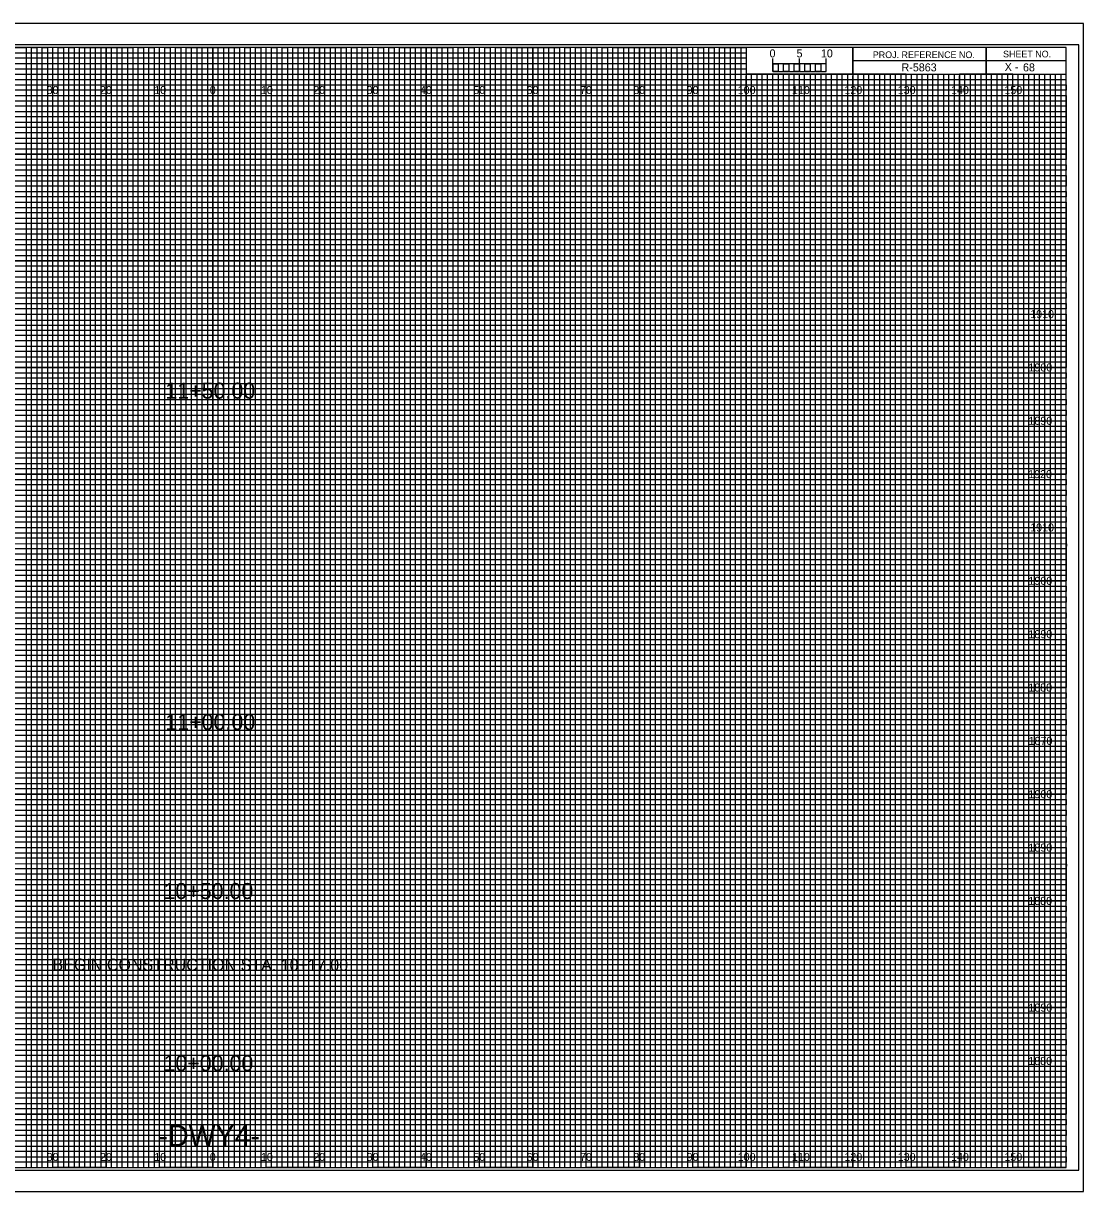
# Model space of a CAD drawing. Extents: x -13 to 323, y -4 to 214.
# Drawn here: x 124.5 to 323.3, y -4.5 to 214.5 of the extents above; entities that cross this region are included whole.
import ezdxf

# ---------------------------------------------------------------- set-up
doc = ezdxf.new("R2010")
doc.units = 0
for name, color, linetype in [('Prop XS Alignment Label', 7, 'Continuous'), ('Prop XS Bar Scale Labels', 7, 'Continuous'), ('Prop XS Elevation Labels', 7, 'Continuous'), ('Prop XS Offset Labels', 7, 'Continuous'), ('Prop XS Project Number', 7, 'Continuous'), ('Prop XS SE Text', 7, 'Continuous'), ('Prop XS Sheet Number', 7, 'Continuous'), ('Prop XS Station Labels', 7, 'Continuous'), ('Sheet Cross Section CELL', 7, 'Continuous'), ('Sheet Cross Section Grid Major CELL', 7, 'Continuous'), ('Sheet Cross Section Grid Middle CELL', 7, 'Continuous'), ('Sheet Cross Section Grid Minor 1 CELL', 7, 'Continuous'), ('Sheet Cross Section Grid Minor 2 CELL', 7, 'Continuous'), ('Sheet Cross Section Scale CELL', 7, 'Continuous'), ('Sheet Cutting Line CELL', 7, 'Continuous'), ('Sheet DOT Grid CELL', 7, 'Continuous'), ('Sheet Plot Border Inside CELL', 7, 'Continuous'), ('Sheet Plot Border Outside CELL', 7, 'Continuous')]:
    doc.layers.add(name, color=color, linetype=linetype)

msp = doc.modelspace()

# ---------------------------------------------------------------- linework, layer by layer
at = {"layer": 'Sheet Cross Section CELL'}
for p, q in [((305, 210), (305, 205)), ((305, 205), (305, 210)), ((280, 207.5), (280, 205)), ((320, 207.49), (280, 207.49)), ((280, 205), (320, 205))]:
    msp.add_line(p, q, dxfattribs=at)
for points in [[(320, 210), (0, 210), (0, 0), (320, 0)], [(280, 210), (260, 210), (260, 205.03), (280, 205.03)], [(320, 210), (280, 210), (280, 205), (320, 205)]]:
    msp.add_lwpolyline(points, close=True, dxfattribs=at)
at = {"layer": 'Sheet Cross Section Grid Major CELL'}
for p, q in [((130, 210), (120, 210)), ((130, 0), (130, 210)), ((150, 210), (140, 210)), ((140, 210), (140, 0)), ((150, 0), (150, 210)), ((170, 210), (160, 210)), ((160, 210), (160, 0)), ((170, 0), (170, 210)), ((190, 210), (180, 210)), ((180, 210), (180, 0)), ((190, 0), (190, 210)), ((210, 210), (200, 210)), ((200, 210), (200, 0)), ((210, 0), (210, 210)), ((230, 210), (220, 210)), ((220, 210), (220, 0)), ((230, 0), (230, 210)), ((250, 210), (240, 210)), ((240, 210), (240, 0)), ((250, 0), (250, 210)), ((260, 210), (260, 0)), ((270, 0), (270, 205)), ((290, 205), (280, 205)), ((280, 205), (280, 0)), ((290, 0), (290, 205)), ((310, 205), (300, 205)), ((300, 205), (300, 0)), ((310, 0), (310, 205)), ((140, 0), (130, 0)), ((160, 0), (150, 0)), ((180, 0), (170, 0)), ((200, 0), (190, 0)), ((220, 0), (210, 0)), ((240, 0), (230, 0)), ((260, 0), (250, 0)), ((280, 0), (270, 0)), ((300, 0), (290, 0)), ((320, 0), (310, 0)), ((320, 0), (320, 0))]:
    msp.add_line(p, q, dxfattribs=at)
for points in [[(0, 200), (320, 200), (320, 190), (0, 190)], [(0, 180), (320, 180), (320, 170), (0, 170)], [(0, 160), (320, 160), (320, 150), (0, 150)], [(0, 140), (320, 140), (320, 130), (0, 130)], [(0, 120), (320, 120), (320, 110), (0, 110)], [(0, 100), (320, 100), (320, 90), (0, 90)], [(0, 80), (320, 80), (320, 70), (0, 70)], [(0, 60), (320, 60), (320, 50), (0, 50)], [(0, 40), (320, 40), (320, 30), (0, 30)], [(0, 20), (320, 20), (320, 10), (0, 10)]]:
    msp.add_lwpolyline(points, dxfattribs=at)
at = {"layer": 'Sheet Cross Section Grid Middle CELL'}
for points in [[(115, 210), (125, 210), (125, 0), (135, 0), (135, 210), (145, 210), (145, 0), (155, 0), (155, 210), (165, 210), (165, 0), (175, 0), (175, 210), (185, 210), (185, 0), (195, 0), (195, 210), (205, 210), (205, 0), (215, 0), (215, 210), (225, 210), (225, 0), (235, 0), (235, 210), (245, 210), (245, 0), (255, 0), (255, 210), (259.93, 210), (260, 210), (260, 205), (264.99, 205), (264.99, 0), (275, 0), (275, 205), (285, 205), (285, 0), (295, 0), (295, 205), (305, 205), (305, 0), (315, 0), (315, 205)], [(0, 205), (275, 205)], [(0, 185), (320, 185), (320, 195), (0, 195)], [(0, 165), (320, 165), (320, 175), (0, 175)], [(0, 145), (320, 145), (320, 155), (0, 155)], [(0, 125), (320, 125), (320, 135), (0, 135)], [(0, 105), (320, 105), (320, 115), (0, 115)], [(0, 85), (320, 85), (320, 95), (0, 95)], [(0, 65), (320, 65), (320, 75), (0, 75)], [(0, 45), (320, 45), (320, 55), (0, 55)], [(0, 25), (320, 25), (320, 35), (0, 35)], [(0, 5), (320, 5), (320, 15), (0, 15)]]:
    msp.add_lwpolyline(points, dxfattribs=at)
at = {"layer": 'Sheet Cross Section Grid Minor 1 CELL'}
for p, q in [((0, 209), (260, 209)), ((260, 209), (260, 207.98)), ((260, 207.98), (0, 207.98)), ((0, 207), (260, 207)), ((260, 205.89), (0, 205.89)), ((260, 207), (260, 205.89)), ((0, 204), (320, 204))]:
    msp.add_line(p, q, dxfattribs=at)
for points in [[(0, 203), (270, 203), (320, 203), (320, 202), (0, 202)], [(0, 201), (320, 201), (320, 199), (0, 199)], [(0, 198), (320, 198), (320, 197), (0, 196.98)], [(0, 196), (320, 196), (320, 194), (0, 194)], [(0, 193), (320, 193), (320, 192), (0, 192)], [(0, 191), (320, 191), (320, 189), (0, 189)], [(0, 188), (320, 188), (320, 187), (0, 187)], [(0, 186), (320, 186), (320, 184), (0, 184)], [(0, 183), (320, 183), (320, 182), (0, 182)], [(0, 181), (320, 181), (320, 179), (0, 179)], [(0, 178), (320, 178), (320, 177), (0, 177)], [(0, 176), (320, 176), (320, 173.95), (320, 173), (320, 172), (0, 172)], [(0, 174), (320, 174), (320, 173), (0, 173)], [(0, 171), (320, 171), (320, 169), (0, 169.03)], [(0, 169.03), (320, 169), (320, 168), (0, 168)], [(0, 167), (320, 167), (320, 166), (0, 166)], [(0, 164), (320, 164), (320, 163), (0, 163)], [(0, 162), (320, 162), (320, 161), (0, 161)], [(-0.07, 158.89), (320, 158.89), (320, 157.88), (-0.07, 157.88)], [(0, 157), (320, 157), (320, 156), (0, 156)], [(0, 154), (320, 154), (320, 153), (0, 153)], [(0, 152), (320, 152), (320, 151), (0, 151)], [(0, 149), (320, 149), (320, 148), (0, 148)], [(0, 147), (320, 147), (320, 146), (0, 146)], [(0, 144), (320, 144), (320, 143), (0, 143)], [(0, 142), (320, 142), (320, 141), (0, 141)], [(0, 139), (320, 139), (319.99, 137.98), (0, 138)], [(0, 137), (320, 137), (320, 136), (0, 136)], [(0, 134), (320, 134), (320, 133), (0, 133)], [(0, 132), (320, 132), (320, 131), (0, 131)], [(0, 129), (320, 129), (320, 128), (0, 128)], [(0, 127), (320, 127), (320, 126), (0, 126)], [(0, 124), (320, 124), (320, 123), (0, 123)], [(0, 122), (320, 122), (320, 121), (0, 121)], [(0, 119), (320, 119), (320, 118), (0, 118)], [(0, 116.99), (320.07, 116.91), (320, 116), (0, 116)], [(0, 114), (320, 114), (320, 113), (0, 113)], [(0, 112), (320, 112), (320, 111), (0, 111)], [(0, 109), (320, 109), (320, 108), (0, 108)], [(0, 107), (320, 107), (320, 106), (0, 106)], [(0, 104), (320, 104), (320, 103), (0, 103)], [(0, 102), (320, 102), (320, 101), (0, 101)], [(0, 99), (320, 99), (320, 98), (0, 98)], [(0, 97), (320, 97), (320, 96), (0, 96)], [(0, 94), (320, 94), (320, 93), (0, 93)], [(0, 92), (320, 92), (320, 91), (0, 91)], [(0, 89), (320, 89), (320, 88), (0, 88)], [(0, 87), (320, 87), (320, 86), (0, 86)], [(0, 84), (320, 84), (320, 83), (0, 83)], [(0, 82), (320, 82), (320, 81), (0, 81)], [(0, 79), (320, 79), (319.99, 77.98), (0, 78)], [(0, 77), (320, 77), (320, 76), (0, 76)], [(0, 74), (320, 74), (320, 73), (0, 73)], [(0, 72), (320, 72), (320, 71), (0, 71)], [(0, 69), (320, 69), (320, 68), (0, 68)], [(0, 67), (320, 67), (320, 66), (0, 66)], [(0, 64), (320, 64), (320, 63), (0, 63)], [(0, 62), (320, 62), (320, 61), (0, 61)], [(0, 59), (320, 59), (320, 58), (0, 58)], [(0, 56.99), (320.07, 56.91), (320, 56), (0, 56)], [(0, 54), (320, 54), (320, 53), (0, 53)], [(0, 52), (320, 52), (320, 51), (0, 51)], [(0, 49), (320, 49), (320, 48), (0, 48)], [(0, 47), (320, 47), (320, 46), (0, 46)], [(0, 44), (320, 44), (320, 43), (0, 43)], [(0, 42), (320, 42), (320, 41), (0, 41)], [(0, 39), (320, 39), (320, 38), (0, 38)], [(0, 37), (320, 37), (320, 36), (0, 36)], [(0, 34), (320, 34), (320, 33), (0, 33)], [(0, 32), (320, 32), (320, 31), (0, 31)], [(0, 29), (320, 29), (320, 28), (0, 28)], [(0, 27), (320, 27), (320, 26), (0, 26)], [(0, 24), (320, 24), (320, 23), (0, 23)], [(0, 22), (320, 22), (320, 21), (0, 21)], [(0, 19), (320, 19), (320, 18), (0, 18)], [(0, 17), (320, 17), (320, 16), (0, 16)], [(0, 14), (320, 14), (320, 13), (0, 13)], [(0, 12), (320, 12), (320, 11), (0, 11)], [(0, 9), (320, 9), (320, 8), (0, 8)], [(0, 7), (320, 7), (320, 6), (0, 6)], [(0, 4), (320, 4), (320, 3), (0, 3)], [(0, 2), (320, 2), (320, 1), (0, 1)]]:
    msp.add_lwpolyline(points, dxfattribs=at)
at = {"layer": 'Sheet Cross Section Grid Minor 2 CELL'}
for p, q in [((267, 205), (266.01, 205)), ((266.01, 205), (266.01, 0)), ((267, 0), (267, 205)), ((269, 205), (268, 205)), ((268, 205), (268, 0)), ((269, 0), (269, 205)), ((266.01, 0), (265, 0)), ((268, 0), (267, 0))]:
    msp.add_line(p, q, dxfattribs=at)
for points in [[(125, 0), (126, 0), (126, 210), (127, 210), (127, 0)], [(127, 0), (128, 0), (128, 210), (129, 210), (129, 0)], [(130, 0), (131, 0), (131, 210), (132, 210), (132, 0)], [(132, 0), (133, 0), (133, 210), (134, 210), (134, 0)], [(135, 0), (136, 0), (136, 210), (137, 210), (137, 0)], [(137, 0), (138, 0), (138, 210), (139, 210), (139, 0)], [(140, 0), (141, 0), (141, 210), (142, 210), (142, 0)], [(142, 0), (143, 0), (143, 210), (144, 210), (144, 0)], [(145, 0), (146, 0), (146, 210), (147, 210), (147, 0)], [(147, 0), (148, 0), (148, 210), (149, 210), (149, 0)], [(150, 0), (151, 0), (151, 210), (152, 210), (152, 0)], [(152, 0), (153, 0), (153, 210), (154, 210), (154, 0)], [(155, 0), (156, 0), (156, 210), (157, 210), (157, 0)], [(157, 0), (158, 0), (158, 210), (159, 210), (159, 0)], [(160, 0), (161, 0), (161, 210), (162, 210), (162, 0)], [(162, 0), (163, 0), (163, 210), (164, 210), (164, 0)], [(165, 0), (166, 0), (166, 210), (167, 210), (167, 0)], [(167, 0), (168, 0), (168, 210), (169, 210), (169, 0)], [(170, 0), (171, 0), (171, 210), (172, 210), (172, 0)], [(172, 0), (173, 0), (173, 210), (174, 210), (174, 0)], [(175, 0), (176, 0), (176, 210), (177, 210), (177, 0)], [(177, 0), (178, 0), (178, 210), (179, 210), (179, 0)], [(180, 0), (181, 0), (181, 210), (182, 210), (182, 0)], [(182, 0), (183, 0), (183, 210), (184, 210), (184, 0)], [(185, 0), (186, 0), (186, 210), (187, 210), (187, 0)], [(187, 0), (188, 0), (188, 210), (189, 210), (189, 0)], [(190, 0), (191, 0), (191, 210), (192, 210), (192, 0)], [(192, 0), (193, 0), (193, 210), (194, 210), (194, 0)], [(195, 0), (196, 0), (196, 210), (197, 210), (197, 0)], [(197, 0), (198, 0), (198, 210), (199, 210), (199, 0)], [(200, 0), (201, 0), (201, 210), (202, 210), (202, 0)], [(202, 0), (203, 0), (203, 210), (204, 210), (204, 0)], [(205, 0), (206, 0), (206, 210), (207, 210), (207, 0)], [(207, 0), (208, 0), (208, 210), (209, 210), (209, 0)], [(210, 0), (211, 0), (211, 210), (212, 210), (212, 0)], [(212, 0), (213, 0), (213, 210), (214, 210), (214, 0)], [(215, 0), (216, 0), (216, 210), (217, 210), (217, 0)], [(217, 0), (218, 0), (218, 210), (219, 210), (219, 0)], [(220, 0), (221, 0), (221, 210), (222, 210), (222, 0)], [(222, 0), (223, 0), (223, 210), (224, 210), (224, 0)], [(225, 0), (226, 0), (226, 210), (227, 210), (227, 0)], [(227, 0), (228, 0), (228, 210), (229, 210), (229, 0)], [(230, 0), (231, 0), (231, 210), (232, 210), (232, 0)], [(232, 0), (233, 0), (233, 210), (234, 210), (234, 0)], [(235, 0), (236, 0), (236, 210), (237, 210), (237, 0)], [(237, 0), (238, 0), (238, 210), (239, 210), (239, 0)], [(240, 0), (241, 0), (241, 210), (242, 210), (242, 0)], [(242, 0), (243, 0), (243, 210), (244, 210), (244, 0)], [(245, 0), (246, 0), (246, 210), (247, 210), (247, 0)], [(247, 0), (248, 0), (248, 210), (249, 210), (249, 0)], [(250, 0), (251, 0), (251, 210), (252, 210), (252, 0)], [(252, 0), (253, 0), (253, 210), (254, 210), (254, 0)], [(255, 0), (256, 0), (256, 210), (257, 210), (257, 0)], [(257, 0), (258, 0), (258, 210), (259, 210), (259, 0)], [(260, 0), (261, 0), (261, 205), (262.02, 205), (262.02, 0)], [(262, 0), (263, 0), (263, 205), (263.99, 205), (263.99, 0)], [(270, 0), (270.98, 0), (270.98, 205), (272, 205), (272, 0)], [(272, 0), (273, 0), (273, 205), (274.05, 205), (274.05, 0)], [(275, 0), (276, 0), (276, 205), (277, 205), (277, 0)], [(277, 0), (278, 0), (278, 205), (279, 205), (279, 0)], [(280, 0), (281, 0), (281, 205), (282, 205), (282, 0)], [(282, 0), (283, 0), (283, 205), (284, 205), (284, 0)], [(285, 0), (286, 0), (286, 205), (287, 205), (287, 0)], [(287, 0), (288, 0), (288, 205), (289, 205), (289, 0)], [(290, 0), (291, 0), (291, 205), (292, 205), (292, 0)], [(292, 0), (293, 0), (293, 205), (294, 205), (294, 0)], [(295, 0), (296, 0), (296, 205), (297, 205), (297, 0)], [(297, 0), (298, 0), (298, 205), (299, 205), (299, 0)], [(300, 0), (301, 0), (301, 205), (302, 205), (302, 0)], [(302, 0), (303, 0), (303, 205), (304, 205), (304, 0)], [(305, 0), (306, 0), (306, 205), (307, 205), (307, 0)], [(307, 0), (308, 0), (308, 205), (309, 205), (309, 0)], [(310, 0), (311, 0), (311, 205), (312, 205), (312, 0)], [(312, 0), (313, 0), (313, 205), (314, 205), (314, 0)], [(315, 0), (316, 0), (316, 205), (317, 205), (317, 0)], [(317, 0), (318, 0), (318, 205), (319, 205), (319, 0)]]:
    msp.add_lwpolyline(points, dxfattribs=at)
at = {"layer": 'Sheet Cross Section Scale CELL'}
for p, q in [((265, 205.49), (265, 207.9)), ((265, 206.9), (265, 207.9)), ((270, 205.49), (270, 207.9)), ((275, 205.49), (275, 207.9)), ((275, 206.9), (275, 207.9))]:
    msp.add_line(p, q, dxfattribs=at)
for points in [[(275, 206.9), (265, 206.9), (265, 205.49), (275, 205.49)], [(265, 206.9), (266, 206.9), (266, 205.49), (265, 205.49)], [(267, 206.9), (268, 206.9), (268, 205.49), (267, 205.49)], [(269, 206.9), (270, 206.9), (270, 205.49), (269, 205.49)], [(271, 206.9), (272, 206.9), (272, 205.49), (271, 205.49)], [(273, 206.9), (274, 206.9), (274, 205.49), (273, 205.49)]]:
    msp.add_lwpolyline(points, close=True, dxfattribs=at)
at = {"layer": 'Sheet Cutting Line CELL'}
for p, q in [((323.3, 214.5), (-13.4, 214.5)), ((-13.4, -4.5), (323.3, -4.5))]:
    msp.add_line(p, q, dxfattribs=at)
at = {"layer": 'Sheet DOT Grid CELL'}
for p, q in [((130, 0), (130, 210)), ((140, 0), (140, 210)), ((150, 0), (150, 210)), ((160, 0), (160, 210)), ((170, 0), (170, 210)), ((180, 0), (180, 210)), ((190, 0), (190, 210)), ((200, 0), (200, 210)), ((210, 0), (210, 210)), ((220, 0), (220, 210)), ((230, 0), (230, 210)), ((240, 0), (240, 210)), ((250, 0), (250, 210)), ((260, 0), (260, 204.69)), ((270, 0), (270, 204.69)), ((280, 0), (280, 204.69)), ((290, 0), (290, 204.69)), ((300, 0), (300, 204.69)), ((310, 0), (310, 204.69)), ((0, 200), (320, 200)), ((0, 190), (320, 190)), ((0, 180), (320, 180)), ((0, 170), (320, 170)), ((0, 160), (320, 160)), ((0, 150), (320, 150)), ((0, 140), (320, 140)), ((0, 130), (320, 130)), ((0, 120), (320, 120)), ((0, 110), (320, 110)), ((0, 100), (320, 100)), ((0, 90), (320, 90)), ((0, 80), (320, 80)), ((0, 70), (320, 70)), ((0, 60), (320, 60)), ((0, 50), (320, 50)), ((0, 40), (320, 40)), ((0, 30), (320, 30)), ((0, 20), (320, 20)), ((0, 10), (320, 10))]:
    msp.add_line(p, q, dxfattribs=at)
at = {"layer": 'Sheet Plot Border Inside CELL'}
msp.add_lwpolyline([(-10.8, -0.5), (322.4, -0.5), (322.4, 210.5), (-10.8, 210.5)], close=True, dxfattribs=at)
at = {"layer": 'Sheet Plot Border Outside CELL'}
msp.add_lwpolyline([(-13.4, -4.5), (323.3, -4.5), (323.3, 214.5), (-13.4, 214.5)], close=True, dxfattribs=at)

# ---------------------------------------------------------------- texts
at = {"layer": 'Prop XS Alignment Label'}
msp.add_text('-DWY4-', height=4, dxfattribs=at).set_placement((149.85, 4))
at = {"layer": 'Prop XS Bar Scale Labels'}
for s, p in [('5', (269.47, 208.12)), ('10', (274.04, 208.12))]:
    msp.add_text(s, height=1.5, dxfattribs=at).set_placement(p)
at = {"layer": 'Prop XS Elevation Labels'}
for s, p in [('1910', (313.28, 159.25)), ('1900', (312.95, 149.25)), ('1890', (312.95, 139.25)), ('1920', (312.9, 129.25)), ('1910', (313.28, 119.25)), ('1900', (312.95, 109.25)), ('1890', (312.95, 99.25)), ('1880', (312.92, 89.25)), ('1870', (312.98, 79.25)), ('1900', (312.95, 69.25)), ('1890', (312.95, 59.25)), ('1880', (312.92, 49.25)), ('1890', (312.95, 29.25)), ('1880', (312.92, 19.25))]:
    msp.add_text(s, height=1.5, dxfattribs=at).set_placement(p)
at = {"layer": 'Prop XS Offset Labels'}
for s, p in [('30', (128.86, 201.25)), ('20', (138.86, 201.25)), ('10', (149.04, 201.25)), ('0', (159.45, 201.25)), ('0', (159.45, 201.25)), ('10', (169.04, 201.25)), ('20', (178.86, 201.25)), ('30', (188.86, 201.25)), ('40', (198.86, 201.25)), ('50', (208.86, 201.25)), ('60', (218.86, 201.25)), ('70', (228.86, 201.25)), ('80', (238.86, 201.25)), ('90', (248.86, 201.25)), ('100', (258.44, 201.25)), ('110', (268.62, 201.25)), ('120', (278.44, 201.25)), ('130', (288.44, 201.25)), ('140', (298.44, 201.25)), ('150', (308.44, 201.25)), ('30', (128.86, 1.25)), ('20', (138.86, 1.25)), ('10', (149.04, 1.25)), ('0', (159.45, 1.25)), ('0', (159.45, 1.25)), ('10', (169.04, 1.25)), ('20', (178.86, 1.25)), ('30', (188.86, 1.25)), ('40', (198.86, 1.25)), ('50', (208.86, 1.25)), ('60', (218.86, 1.25)), ('70', (228.86, 1.25)), ('80', (238.86, 1.25)), ('90', (248.86, 1.25)), ('100', (258.44, 1.25)), ('110', (268.62, 1.25)), ('120', (278.44, 1.25)), ('130', (288.44, 1.25)), ('140', (298.44, 1.25)), ('150', (308.44, 1.25))]:
    msp.add_text(s, height=1.5, dxfattribs=at).set_placement(p)
at = {"layer": 'Prop XS Project Number'}
msp.add_text('R-5863', height=1.5, dxfattribs=at).set_placement((289.16, 205.5))
at = {"layer": 'Prop XS SE Text'}
msp.add_text('BEGIN CONSTRUCTION STA. 10+17.00', height=2.25, rotation=359.9225, dxfattribs=at).set_placement((129.96, 36.94))
at = {"layer": 'Prop XS Sheet Number'}
msp.add_text('68', height=1.5, dxfattribs=at).set_placement((311.93, 205.5))
at = {"layer": 'Prop XS Station Labels'}
for s, p in [('11+50.00', (151.13, 144.15)), ('11+00.00', (151.13, 82.04)), ('10+50.00', (150.77, 50.35)), ('10+00.00', (150.77, 18.08))]:
    msp.add_text(s, height=3, dxfattribs=at).set_placement(p)
at = {"layer": 'Sheet Cross Section CELL'}
for s, height, p in [('PROJ. REFERENCE NO.', 1.25, (283.77, 207.99)), ('SHEET NO.', 1.25, (308.19, 208.12)), ('X -    ', 1.5, (308.5, 205.58))]:
    msp.add_text(s, height=height, dxfattribs=at).set_placement(p)
at = {"layer": 'Sheet Cross Section Scale CELL'}
msp.add_text('0', height=1.5, dxfattribs=at).set_placement((264.41, 208.12))

doc.saveas('drawing.dxf')
